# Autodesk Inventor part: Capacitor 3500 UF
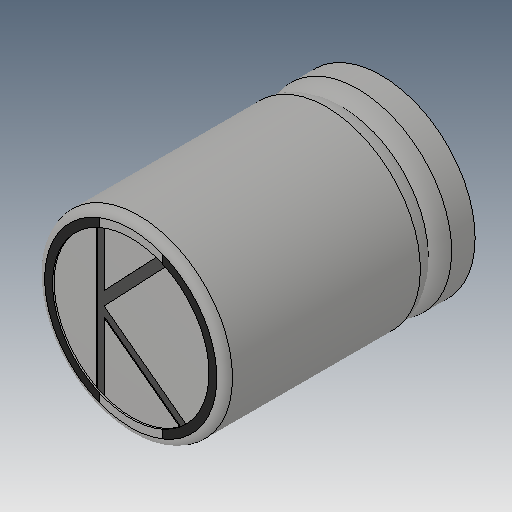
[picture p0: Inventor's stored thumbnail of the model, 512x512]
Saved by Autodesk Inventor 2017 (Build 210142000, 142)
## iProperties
Created: 2005-12
Part Number: Capacitor 3500 UF
Material: Generic
Document SubType Name: Modeling
Designer: DanielSeverino
Density: 1 g/cm^3
Appearance: Default
Author: DanielSeverino
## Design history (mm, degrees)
feature "Solid1"
body "Solid2"
